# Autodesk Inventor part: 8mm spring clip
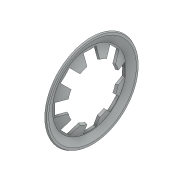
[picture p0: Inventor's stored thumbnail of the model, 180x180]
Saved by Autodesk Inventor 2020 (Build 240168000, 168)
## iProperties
Created: 2020-01
Part Number: 8mm spring clip
Material: Steel, High Strength, Low Alloy
Document SubType Name: Modeling
Designer: woodk
Density: 7.85 g/cm^3
Appearance: Steel - Polished
Vendor: KoP
Mass: 0.292699 g
Surface Area: 2.34135 cm^2
Volume: 0.0372865 cm^3
Author: woodk
Revision Number: ANY
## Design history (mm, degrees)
feature "Imported1"
body "Solid1"
